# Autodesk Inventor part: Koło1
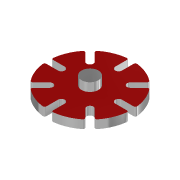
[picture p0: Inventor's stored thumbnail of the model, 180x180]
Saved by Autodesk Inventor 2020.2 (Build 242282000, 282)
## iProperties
Created: 2005-10
Part Number: Koło1
Document SubType Name: Modeling
Designer: F.Stasiak
Density: 1 g/cm^3
Material: Ogólny
Appearance: Chrom — polerowany
Manager: www.cadconsulting.pl
Company: Fabian Stasiak CAD Consulting
Author: F.Stasiak
Subject: Zbiór ćwiczeń. Autodesk Inventor 2020. Kurs podstawowy
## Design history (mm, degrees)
sketch "Szkic1"
  geometry: C1 r 50 at (0, 0); 1 further point
  constraints: 1 centre point, 1 coincident
  dimensions: "d0" = 100 diameter of C1
extrude "Wyciągnięcie proste1" new body sketch "Szkic1" stored distance "d1" = 10; taper "d2" = 0 deg
sketch "Szkic2"
  geometry: C1 r 10 at (0, 0); 1 further point
  constraints: 1 centre point, 1 coincident
  dimensions: "d3" = 20 diameter of C1
extrude "Wyciągnięcie proste2" join sketch "Szkic2" stored distance "d4" = 30; taper "d5" = 0 deg
sketch "Szkic3"
  geometry: L1 (-4, 49.84)-(-4, 33.84); L2 (4, 33.84)-(4, 49.84); L3 (0, 0)-(0, 50); A1 r 50 centre (0, 0) between (-4, 49.84) and (4, 49.84) reference; A2 r 4 centre (0, 33.84) between (-4, 33.84) and (4, 33.84)
  constraints: 6 end point, 5 point on circle, 2 parallel, 2 tangent, 1 centre point, 1 point on line, 1 vertical
  dimensions: "d6" = 4 radius of A2; "d7" = 16 distance of L2.start L2.end
extrude "Wyciągnięcie proste3" cut sketch "Szkic3" extent not by distance; stored distance "d8" = 30; taper "d9" = 0 deg
fillet "Zaokrąglenie1" dims "d10" = 2
pattern_circular "Szyk kołowy1" dims angle "d12" = 360 deg
node "Bryła1"
node "Korpusy bryłowe"
node "Korpusy powierzchniowe"
